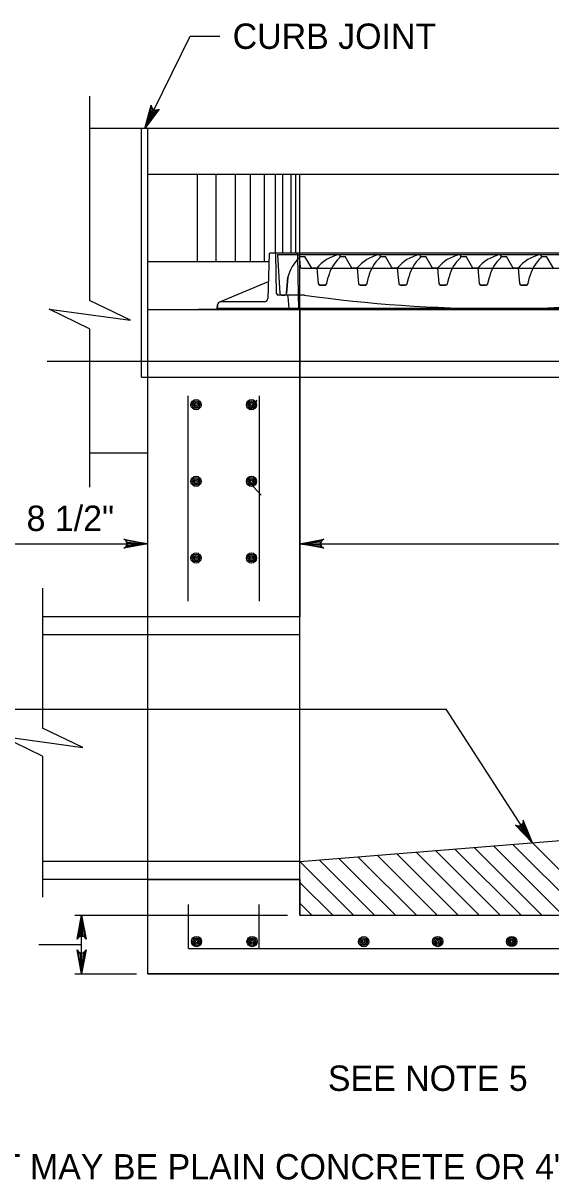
# Model space of a CAD drawing. Extents: x 2.4 to 9.7, y 1.1 to 11.2.
# Drawn here: x 5.797 to 7.045, y 8.136 to 10.871 of the extents above; entities that cross this region are included whole.
import ezdxf

# ---------------------------------------------------------------- set-up
doc = ezdxf.new("R2010")
doc.units = 0
for name, color, linetype in [('DETL-DIMS', 7, 'Continuous'), ('DETL-LINE', 7, 'Continuous'), ('DETL-NOTE', 7, 'Continuous'), ('DETL-PATT', 7, 'Continuous')]:
    doc.layers.add(name, color=color, linetype=linetype)

msp = doc.modelspace()

# ---------------------------------------------------------------- linework, layer by layer
at = {"layer": 'DETL-DIMS'}
for p, q in [((6.0843, 10.6218), (6.1921, 10.84)), ((6.1921, 10.84), (6.262, 10.84)), ((7.3624, 10.0708), (5.8534, 10.0708)), ((5.6957, 9.6398), (6.0916, 9.6398)), ((6.4511, 9.6398), (8.4972, 9.6398)), ((5.491, 9.2486), (6.7976, 9.2486)), ((7.0012, 8.9325), (6.7976, 9.2486)), ((5.9187, 8.7614), (6.4218, 8.7614)), ((5.9351, 8.6227), (5.9351, 8.7614)), ((5.9351, 8.6914), (5.8338, 8.6914)), ((5.9187, 8.6227), (6.0645, 8.6227))]:
    msp.add_line(p, q, dxfattribs=at)
for points in [[(6.0843, 10.6218), (6.0998, 10.6771), (6.1006, 10.6719), (6.103, 10.6682), (6.1061, 10.6659), (6.1098, 10.6648), (6.1142, 10.6652), (6.1188, 10.6677), (6.0843, 10.6218), (6.1142, 10.6652), (6.1098, 10.6648), (6.0843, 10.6218), (6.1061, 10.6659), (6.103, 10.6682), (6.0843, 10.6218), (6.1006, 10.6719)], [(5.9539, 10.1482), (5.8586, 10.1948), (6.0508, 10.1687), (5.9539, 10.2148)], [(6.0916, 9.6398), (6.0351, 9.6292), (6.0394, 9.6322), (6.0417, 9.636), (6.0423, 9.6398), (6.0417, 9.6436), (6.0394, 9.6474), (6.0351, 9.6504), (6.0916, 9.6398), (6.0394, 9.6474), (6.0417, 9.6436), (6.0916, 9.6398), (6.0423, 9.6398), (6.0417, 9.636), (6.0916, 9.6398), (6.0394, 9.6322)], [(6.4511, 9.6398), (6.5076, 9.6504), (6.5033, 9.6474), (6.501, 9.6436), (6.5004, 9.6398), (6.501, 9.636), (6.5033, 9.6322), (6.5076, 9.6292), (6.4511, 9.6398), (6.5033, 9.6322), (6.501, 9.636), (6.4511, 9.6398), (6.5004, 9.6398), (6.501, 9.6436), (6.4511, 9.6398), (6.5033, 9.6474)], [(5.8425, 9.1372), (5.7458, 9.1845), (5.938, 9.1584), (5.8425, 9.2038)], [(7.0012, 8.9325), (6.9795, 8.9858), (6.9793, 8.9805), (6.9774, 8.9765), (6.9745, 8.9739), (6.971, 8.9724), (6.9666, 8.9723), (6.9617, 8.9743), (7.0012, 8.9325), (6.9666, 8.9723), (6.971, 8.9724), (7.0012, 8.9325), (6.9745, 8.9739), (6.9774, 8.9765), (7.0012, 8.9325), (6.9793, 8.9805)], [(5.9351, 8.7614), (5.9457, 8.7049), (5.9427, 8.7092), (5.9389, 8.7115), (5.9351, 8.7121), (5.9313, 8.7115), (5.9275, 8.7092), (5.9245, 8.7049), (5.9351, 8.7614), (5.9275, 8.7092), (5.9313, 8.7115), (5.9351, 8.7614), (5.9351, 8.7121), (5.9389, 8.7115), (5.9351, 8.7614), (5.9427, 8.7092)], [(5.9351, 8.6227), (5.9245, 8.6792), (5.9275, 8.6748), (5.9313, 8.6726), (5.9351, 8.6719), (5.9389, 8.6726), (5.9427, 8.6748), (5.9457, 8.6792), (5.9351, 8.6227), (5.9427, 8.6748), (5.9389, 8.6726), (5.9351, 8.6227), (5.9351, 8.6719), (5.9313, 8.6726), (5.9351, 8.6227), (5.9275, 8.6748)]]:
    msp.add_lwpolyline(points, dxfattribs=at)
at = {"layer": 'DETL-LINE'}
for p, q in [((5.9539, 10.6983), (5.9539, 10.2148)), ((5.9539, 10.6227), (9.0468, 10.6227)), ((6.077, 10.0336), (6.077, 10.6227)), ((6.0916, 9.4666), (6.0916, 10.6227)), ((6.0916, 10.5136), (8.8568, 10.5136)), ((6.2088, 10.3073), (6.2088, 10.5136)), ((6.2535, 10.3073), (6.2535, 10.5136)), ((6.2991, 10.3073), (6.2991, 10.5136)), ((6.3348, 10.3073), (6.3348, 10.5136)), ((6.3676, 10.3073), (6.3676, 10.5136)), ((6.3934, 10.3269), (6.3934, 10.5136)), ((6.4112, 10.3269), (6.4112, 10.5136)), ((6.4311, 10.3269), (6.4311, 10.5136)), ((6.442, 10.3269), (6.442, 10.5136)), ((6.4511, 8.7614), (6.4511, 10.5136)), ((6.3785, 10.325), (6.3753, 10.2195)), ((6.3785, 10.325), (6.3753, 10.2195)), ((7.4642, 10.3269), (6.3805, 10.3269)), ((6.3925, 10.3269), (6.3805, 10.3269)), ((6.3963, 10.2316), (6.3944, 10.325)), ((6.3963, 10.2316), (6.3944, 10.325)), ((6.4461, 10.323), (6.446, 10.325)), ((6.4479, 10.2277), (6.4461, 10.323)), ((6.4499, 10.323), (6.4517, 10.2949)), ((6.0916, 10.3073), (6.3779, 10.3073)), ((6.4556, 10.2912), (7.3367, 10.2912)), ((6.4912, 10.2912), (6.4945, 10.255)), ((6.5865, 10.2912), (6.5898, 10.255)), ((6.6817, 10.2912), (6.685, 10.255)), ((6.777, 10.2912), (6.7803, 10.255)), ((6.8723, 10.2912), (6.8756, 10.255)), ((6.9675, 10.2912), (6.9708, 10.255)), ((6.3764, 10.2595), (6.2611, 10.2112)), ((6.4199, 10.2314), (6.4232, 10.2705)), ((6.5149, 10.2552), (6.5185, 10.2705)), ((6.6101, 10.2552), (6.6137, 10.2705)), ((6.7054, 10.2552), (6.709, 10.2705)), ((6.8007, 10.2552), (6.8043, 10.2705)), ((6.8959, 10.2552), (6.8995, 10.2705)), ((6.9912, 10.2552), (6.9948, 10.2705)), ((6.4985, 10.2515), (6.5109, 10.2515)), ((6.5937, 10.2515), (6.6062, 10.2515)), ((6.689, 10.2515), (6.7014, 10.2515)), ((6.7843, 10.2515), (6.7967, 10.2515)), ((6.8795, 10.2515), (6.892, 10.2515)), ((6.9748, 10.2515), (6.9872, 10.2515)), ((6.2555, 10.196), (6.2562, 10.2046)), ((6.3673, 10.2118), (6.2641, 10.2118)), ((6.3673, 10.2118), (6.2641, 10.2118)), ((6.4197, 10.2277), (6.4003, 10.2277)), ((6.408, 10.2277), (6.416, 10.2277)), ((6.4262, 10.196), (6.4237, 10.2241)), ((6.4486, 10.196), (6.4479, 10.2277)), ((6.0916, 10.1938), (6.3701, 10.1938)), ((7.4701, 10.196), (6.2555, 10.196)), ((6.3638, 10.1936), (8.8568, 10.1936)), ((5.9539, 10.1482), (5.9539, 9.7735)), ((6.077, 10.0336), (6.0916, 10.0336)), ((6.0916, 10.0336), (6.4511, 10.0336)), ((6.4511, 10.0336), (7.3439, 10.0336)), ((6.1868, 9.504), (6.1868, 9.9898)), ((6.3559, 9.504), (6.3559, 9.9898)), ((6.0916, 9.8543), (5.9539, 9.8543)), ((5.8425, 9.5348), (5.8425, 9.2038)), ((6.4511, 9.4666), (5.8425, 9.4666)), ((6.0916, 8.8462), (6.0916, 9.4666)), ((6.4511, 9.4242), (5.8425, 9.4242)), ((5.8425, 9.1372), (5.8425, 8.8044)), ((6.4511, 8.8886), (8.4972, 9.052)), ((6.4511, 8.8886), (5.8425, 8.8886)), ((6.4511, 8.8462), (5.8425, 8.8462)), ((6.0916, 8.6227), (6.0916, 8.8462)), ((6.188, 8.6829), (6.188, 8.7871)), ((6.3547, 8.6829), (6.3547, 8.7871)), ((6.4511, 8.7614), (8.4972, 8.7614)), ((6.0916, 8.6227), (6.0916, 8.7444)), ((6.188, 8.6829), (6.3547, 8.6829)), ((6.3547, 8.6829), (8.5958, 8.6829)), ((6.0916, 8.6227), (8.8568, 8.6227))]:
    msp.add_line(p, q, dxfattribs=at)
for points in [[(6.4475, 10.323), (6.3984, 10.323), (6.4041, 10.2314)], [(6.2562, 10.2046), (6.2555, 10.196), (6.4262, 10.196), (6.4237, 10.2241)], [(6.4197, 10.2277), (6.416, 10.2277), (6.408, 10.2277), (6.4003, 10.2277)]]:
    msp.add_lwpolyline(points, dxfattribs=at)
for centre, radius in [((6.2057, 9.9686), 0.0121), ((6.2057, 9.9686), 0.00909), ((6.2057, 9.9686), 0.00606), ((6.2057, 9.9686), 0.00303), ((6.337, 9.9686), 0.0121), ((6.337, 9.9686), 0.00909), ((6.337, 9.9686), 0.00606), ((6.337, 9.9686), 0.00303), ((6.2057, 9.7873), 0.0121), ((6.2057, 9.7873), 0.00909), ((6.2057, 9.7873), 0.00606), ((6.337, 9.7873), 0.0121), ((6.337, 9.7873), 0.00909), ((6.337, 9.7873), 0.00606), ((6.2057, 9.7873), 0.00303), ((6.337, 9.7873), 0.00303), ((6.2057, 9.606), 0.0121), ((6.2057, 9.606), 0.00909), ((6.2057, 9.606), 0.00606), ((6.2057, 9.606), 0.00303), ((6.337, 9.606), 0.0121), ((6.337, 9.606), 0.00909), ((6.337, 9.606), 0.00606), ((6.337, 9.606), 0.00303), ((6.2069, 8.699), 0.0121), ((6.2069, 8.699), 0.00909), ((6.2069, 8.699), 0.00606), ((6.2069, 8.699), 0.00303), ((6.3382, 8.699), 0.0121), ((6.3382, 8.699), 0.00909), ((6.3382, 8.699), 0.00606), ((6.3382, 8.699), 0.00303), ((6.6023, 8.6988), 0.0121), ((6.6023, 8.6988), 0.00909), ((6.6023, 8.6988), 0.00606), ((6.6023, 8.6988), 0.00303), ((6.7773, 8.699), 0.0121), ((6.7773, 8.699), 0.00909), ((6.7773, 8.699), 0.00606), ((6.7773, 8.699), 0.00303), ((6.9523, 8.6993), 0.0121), ((6.9523, 8.6993), 0.00909), ((6.9523, 8.6993), 0.00606), ((6.9523, 8.6993), 0.00303)]:
    msp.add_circle(centre, radius, dxfattribs=at)
for centre, radius, start, end in [((6.3805, 10.325), 0.00198, 90, 178.2145), ((6.3805, 10.325), 0.00198, 90, 178.2145), ((6.3925, 10.325), 0.00198, 1.1458, 90), ((6.3925, 10.325), 0.00198, 1.1458, 90), ((6.5095, 10.2502), 0.0887, 132.0547, 166.7971), ((6.444, 10.325), 0.00198, 1.1222, 90), ((6.4475, 10.319), 0.00397, 312.139, 90), ((6.5607, 10.2362), 0.0887, 101.6847, 141.6027), ((6.6048, 10.2502), 0.0887, 132.0547, 166.7971), ((6.5427, 10.319), 0.00397, 312.139, 90), ((6.6559, 10.2362), 0.0887, 101.6847, 141.6027), ((6.7, 10.2502), 0.0887, 132.0547, 166.7971), ((6.638, 10.319), 0.00397, 312.139, 90), ((6.7512, 10.2362), 0.0887, 101.6847, 141.6027), ((6.7953, 10.2502), 0.0887, 132.0547, 166.7971), ((6.7333, 10.319), 0.00397, 312.139, 90), ((6.8465, 10.2362), 0.0887, 101.6847, 141.6027), ((6.8906, 10.2502), 0.0887, 132.0547, 166.7971), ((6.8285, 10.319), 0.00397, 312.139, 90), ((6.9417, 10.2362), 0.0887, 101.6847, 141.6027), ((6.9858, 10.2502), 0.0887, 132.0547, 166.7971), ((6.9238, 10.319), 0.00397, 312.139, 90), ((7.037, 10.2362), 0.0887, 101.6847, 141.6027), ((7.0811, 10.2502), 0.0887, 132.0547, 166.7971), ((7.0191, 10.319), 0.00397, 312.139, 90), ((6.4556, 10.2952), 0.00397, 183.5874, 270.0007), ((6.4003, 10.2317), 0.00397, 181.1458, 270), ((6.4003, 10.2317), 0.00397, 181.1458, 270), ((6.408, 10.2317), 0.00397, 183.5616, 270), ((6.416, 10.2317), 0.00397, 270, 355.2441), ((6.4985, 10.2555), 0.00397, 186.5049, 270), ((6.5109, 10.2555), 0.00397, 270, 356.0265), ((6.5937, 10.2555), 0.00397, 186.5049, 270), ((6.6062, 10.2555), 0.00397, 270, 356.0265), ((6.689, 10.2555), 0.00397, 186.5049, 270), ((6.7014, 10.2555), 0.00397, 270, 356.0265), ((6.7843, 10.2555), 0.00397, 186.5049, 270), ((6.7967, 10.2555), 0.00397, 270, 356.0265), ((6.8795, 10.2555), 0.00397, 186.5049, 270), ((6.892, 10.2555), 0.00397, 270, 356.0265), ((6.9748, 10.2555), 0.00397, 186.5049, 270), ((6.9872, 10.2555), 0.00397, 270, 356.0265), ((6.2641, 10.2039), 0.00794, 90, 175), ((6.2641, 10.2039), 0.00794, 90, 175), ((6.3673, 10.2198), 0.00794, 270, 358.2584), ((6.3673, 10.2198), 0.00794, 270, 358.2584), ((6.4197, 10.2237), 0.00397, 5, 90), ((6.4197, 10.2237), 0.00397, 5, 90)]:
    msp.add_arc(centre, radius, start, end, dxfattribs=at)
at = {"layer": 'DETL-NOTE'}
for p, q in [((6.3785, 10.3269), (6.3785, 10.3269)), ((6.3944, 10.3269), (6.3944, 10.3269)), ((6.3944, 10.3269), (6.3944, 10.3269)), ((7.4463, 10.323), (6.3984, 10.323)), ((6.3984, 10.323), (6.4041, 10.2314)), ((6.3984, 10.323), (6.3984, 10.323)), ((6.4514, 10.319), (6.4633, 10.319)), ((6.4793, 10.2912), (6.4633, 10.319)), ((6.5467, 10.319), (6.5586, 10.319)), ((6.5745, 10.2912), (6.5586, 10.319)), ((6.642, 10.319), (6.6539, 10.319)), ((6.6698, 10.2912), (6.6539, 10.319)), ((6.7372, 10.319), (6.7491, 10.319)), ((6.7651, 10.2912), (6.7491, 10.319)), ((6.8325, 10.319), (6.8444, 10.319)), ((6.8603, 10.2912), (6.8444, 10.319)), ((6.9278, 10.319), (6.9397, 10.319)), ((6.9556, 10.2912), (6.9397, 10.319)), ((7.023, 10.319), (7.0349, 10.319)), ((7.0509, 10.2912), (7.0349, 10.319)), ((6.4912, 10.2912), (6.4793, 10.2912)), ((6.4912, 10.2912), (6.4945, 10.2552)), ((6.5865, 10.2912), (6.5745, 10.2912)), ((6.5865, 10.2912), (6.5898, 10.2552)), ((6.6817, 10.2912), (6.6698, 10.2912)), ((6.6817, 10.2912), (6.685, 10.2552)), ((6.777, 10.2912), (6.7651, 10.2912)), ((6.777, 10.2912), (6.7803, 10.2552)), ((6.8723, 10.2912), (6.8603, 10.2912)), ((6.8723, 10.2912), (6.8756, 10.2552)), ((6.9675, 10.2912), (6.9556, 10.2912)), ((6.9675, 10.2912), (6.9708, 10.2552)), ((6.4232, 10.2705), (6.4199, 10.2314)), ((6.5149, 10.2552), (6.5185, 10.2705)), ((6.6101, 10.2552), (6.6137, 10.2705)), ((6.7054, 10.2552), (6.709, 10.2705)), ((6.8007, 10.2552), (6.8043, 10.2705)), ((6.8959, 10.2552), (6.8995, 10.2705)), ((6.9912, 10.2552), (6.9948, 10.2705)), ((6.5109, 10.2515), (6.4985, 10.2515)), ((6.6062, 10.2515), (6.5937, 10.2515)), ((6.7014, 10.2515), (6.689, 10.2515)), ((6.7967, 10.2515), (6.7843, 10.2515)), ((6.892, 10.2515), (6.8795, 10.2515)), ((6.9872, 10.2515), (6.9748, 10.2515)), ((6.416, 10.2277), (6.408, 10.2277)), ((6.4619, 10.2277), (6.416, 10.2277)), ((6.2555, 10.196), (6.2555, 10.196)), ((6.4262, 10.196), (6.4262, 10.196)), ((6.3498, 9.9791), (6.3337, 9.9567)), ((6.3339, 9.7834), (6.3596, 9.7545))]:
    msp.add_line(p, q, dxfattribs=at)
for centre, radius, start, end in [((6.5095, 10.2502), 0.0887, 132.0547, 166.7971), ((6.4475, 10.319), 0.00397, 312.139, 90), ((6.5607, 10.2362), 0.0887, 101.6847, 141.6027), ((6.6048, 10.2502), 0.0887, 132.0547, 166.7971), ((6.5427, 10.319), 0.00397, 312.139, 90), ((6.6559, 10.2362), 0.0887, 101.6847, 141.6027), ((6.7, 10.2502), 0.0887, 132.0547, 166.7971), ((6.638, 10.319), 0.00397, 312.139, 90), ((6.7512, 10.2362), 0.0887, 101.6847, 141.6027), ((6.7953, 10.2502), 0.0887, 132.0547, 166.7971), ((6.7333, 10.319), 0.00397, 312.139, 90), ((6.8465, 10.2362), 0.0887, 101.6847, 141.6027), ((6.8906, 10.2502), 0.0887, 132.0547, 166.7971), ((6.8285, 10.319), 0.00397, 312.139, 90), ((6.9417, 10.2362), 0.0887, 101.6847, 141.6027), ((6.9858, 10.2502), 0.0887, 132.0547, 166.7971), ((6.9238, 10.319), 0.00397, 312.139, 90), ((7.037, 10.2362), 0.0887, 101.6847, 141.6027), ((7.0811, 10.2502), 0.0887, 132.0547, 166.7971), ((7.0191, 10.319), 0.00397, 312.139, 90), ((6.408, 10.2317), 0.00397, 183.5616, 270), ((6.416, 10.2317), 0.00397, 270, 355.2441), ((6.4985, 10.2555), 0.00397, 183.9735, 270), ((6.5109, 10.2555), 0.00397, 270, 356.0265), ((6.5937, 10.2555), 0.00397, 183.9735, 270), ((6.6062, 10.2555), 0.00397, 270, 356.0265), ((6.689, 10.2555), 0.00397, 183.9735, 270), ((6.7014, 10.2555), 0.00397, 270, 356.0265), ((6.7843, 10.2555), 0.00397, 183.9735, 270), ((6.7967, 10.2555), 0.00397, 270, 356.0265), ((6.8795, 10.2555), 0.00397, 183.9735, 270), ((6.892, 10.2555), 0.00397, 270, 356.0265), ((6.9748, 10.2555), 0.00397, 183.9735, 270), ((6.9872, 10.2555), 0.00397, 270, 356.0265), ((6.9223, 13.5501), 3.3542, 262.1096, 277.8904)]:
    msp.add_arc(centre, radius, start, end, dxfattribs=at)
at = {"layer": 'DETL-PATT'}
for p, q in [((6.8179, 8.9179), (6.9744, 8.7614)), ((6.8637, 8.9216), (7.0239, 8.7614)), ((6.9095, 8.9252), (7.0734, 8.7614)), ((6.9554, 8.9289), (7.1229, 8.7614)), ((7.0012, 8.9325), (7.1744, 8.7593)), ((6.497, 8.8923), (6.6279, 8.7614)), ((6.5428, 8.896), (6.6774, 8.7614)), ((6.5887, 8.8996), (6.7269, 8.7614)), ((6.6345, 8.9033), (6.7764, 8.7614)), ((6.6803, 8.9069), (6.8259, 8.7614)), ((6.7262, 8.9106), (6.8754, 8.7614)), ((6.772, 8.9142), (6.9249, 8.7614)), ((6.4511, 8.8886), (6.5784, 8.7614)), ((6.4511, 8.8391), (6.5289, 8.7614)), ((6.4511, 8.7896), (6.4794, 8.7614))]:
    msp.add_line(p, q, dxfattribs=at)
for points in [[(6.0916, 10.1938), (6.4511, 10.196), (6.4511, 9.4666), (6.0916, 9.4666)], [(6.0916, 8.8462), (6.4511, 8.8462), (6.4511, 8.7614), (8.4972, 8.7614), (8.4972, 10.196), (8.8568, 10.1936), (8.8568, 8.6227), (6.0916, 8.6227)]]:
    msp.add_lwpolyline(points, close=True, dxfattribs=at)

# ---------------------------------------------------------------- texts
at = {"layer": 'DETL-NOTE'}
for s, p in [('CURB JOINT', (6.2923, 10.81)), ('8 1/2"', (5.8049, 9.6701)), ('SEE NOTE 5', (6.5175, 8.346)), ('INVERT MAY BE PLAIN CONCRETE OR 4" BRICK LAID ON EDGE.', (5.4964, 8.1365))]:
    msp.add_text(s, height=0.06, dxfattribs=at).set_placement(p)

doc.saveas('drawing.dxf')
